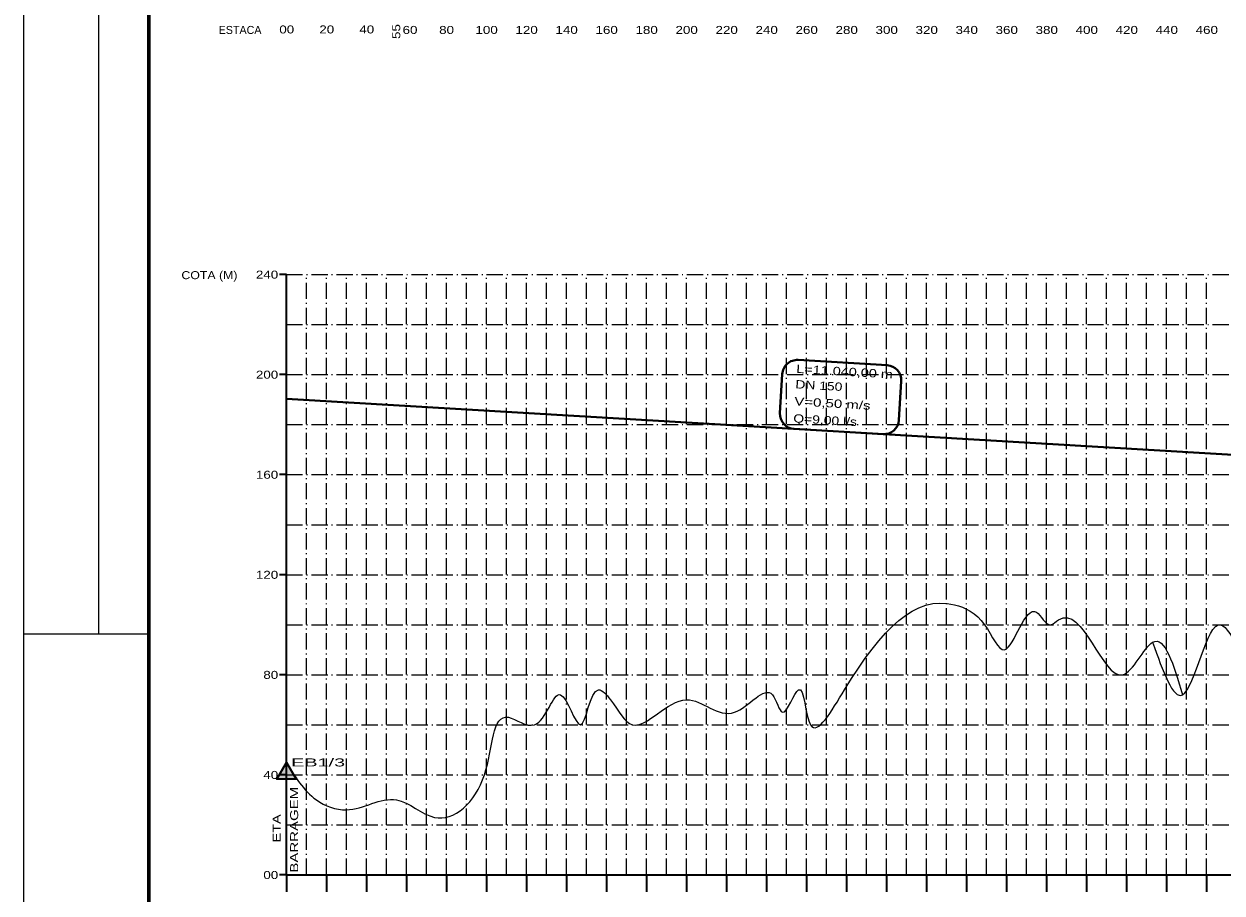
# Model space of a CAD drawing. Extents: x 0 to 1682, y 0 to 1188.
# Drawn here: x -0.2 to 478.9, y 490.3 to 837.7 of the extents above; entities that cross this region are included whole.
import ezdxf
from ezdxf.enums import TextEntityAlignment as Align

# ---------------------------------------------------------------- set-up
doc = ezdxf.new("R2010")
doc.units = 0
doc.header["$LTSCALE"] = 1.3
doc.linetypes.add('DOT_DASHED', pattern=[7.7, 5, -1.2, 0.3, -1.2])
for name, color, linetype, lineweight in [('1', 7, 'DOT_DASHED', 13), ('56', 7, 'Continuous', 13), ('62', 7, 'Continuous', 13), ('63', 7, 'Continuous', 25), ('9', 7, 'Continuous', 40)]:
    doc.layers.add(name, color=color, linetype=linetype, lineweight=lineweight)
doc.layers.add('24', color=7, linetype='Continuous')

msp = doc.modelspace()

# ---------------------------------------------------------------- hatches: boundary and pattern name
at = {"layer": '62'}
msp.add_hatch(color=256, dxfattribs=at).paths.add_polyline_path([(104.775, 542.538), (108.721, 535.8), (100.912, 535.751)])

# ---------------------------------------------------------------- linework, layer by layer
at = {"layer": '1'}
for p, q in [((104.775, 737.538), (914.356, 737.538)), ((112.775, 497.538), (112.775, 737.538)), ((120.775, 497.538), (120.775, 737.538)), ((128.775, 497.538), (128.775, 737.538)), ((136.775, 497.538), (136.775, 737.538)), ((144.775, 497.538), (144.775, 737.538)), ((152.775, 497.538), (152.775, 737.538)), ((160.775, 497.538), (160.775, 737.538)), ((168.775, 497.538), (168.775, 737.538)), ((176.775, 497.538), (176.775, 737.538)), ((184.775, 497.538), (184.775, 737.538)), ((192.775, 497.538), (192.775, 737.538)), ((200.775, 497.538), (200.775, 737.538)), ((208.775, 497.538), (208.775, 737.538)), ((216.775, 497.538), (216.775, 737.538)), ((224.775, 497.538), (224.775, 737.538)), ((232.775, 497.538), (232.775, 737.538)), ((240.775, 497.538), (240.775, 737.538)), ((248.775, 497.538), (248.775, 737.538)), ((256.775, 497.538), (256.775, 737.538)), ((264.775, 497.538), (264.775, 737.538)), ((272.775, 497.538), (272.775, 737.538)), ((280.775, 497.538), (280.775, 737.538)), ((288.775, 497.538), (288.775, 737.538)), ((296.775, 497.538), (296.775, 737.538)), ((304.775, 497.538), (304.775, 737.538)), ((312.775, 497.538), (312.775, 737.538)), ((320.775, 497.538), (320.775, 737.538)), ((328.775, 497.538), (328.775, 737.538)), ((336.775, 497.538), (336.775, 737.538)), ((344.775, 497.538), (344.775, 737.538)), ((352.775, 497.538), (352.775, 737.538)), ((360.775, 497.538), (360.775, 737.538)), ((368.775, 497.538), (368.775, 737.538)), ((376.775, 497.538), (376.775, 737.538)), ((384.775, 497.538), (384.775, 737.538)), ((392.775, 497.538), (392.775, 737.538)), ((400.775, 497.538), (400.775, 737.538)), ((408.775, 497.538), (408.775, 737.538)), ((416.775, 497.538), (416.775, 737.538)), ((424.775, 497.538), (424.775, 737.538)), ((432.775, 497.538), (432.775, 737.538)), ((440.775, 497.538), (440.775, 737.538)), ((448.775, 497.538), (448.775, 737.538)), ((456.775, 497.538), (456.775, 737.538)), ((464.775, 497.538), (464.775, 737.538)), ((472.775, 497.538), (472.775, 737.538)), ((104.775, 717.538), (914.356, 717.538)), ((104.775, 697.538), (914.356, 697.538)), ((104.775, 677.538), (914.356, 677.538)), ((104.775, 657.538), (914.356, 657.538)), ((104.775, 637.538), (914.356, 637.538)), ((104.775, 617.538), (914.356, 617.538)), ((104.775, 597.538), (914.356, 597.538)), ((104.775, 577.538), (914.356, 577.538)), ((104.775, 557.538), (914.356, 557.538)), ((104.775, 537.538), (914.356, 537.538)), ((104.775, 517.538), (914.356, 517.538))]:
    msp.add_line(p, q, dxfattribs=at)
at = {"layer": '56'}
for points in [[(104.775, 542.538), (116.775, 527.538), (128.775, 523.538), (148.775, 527.538), (163.975, 520.538), (183.975, 537.538), (193.575, 560.538), (203.975, 557.538), (214.375, 569.538), (222.375, 557.538), (229.575, 571.538), (234.375, 567.538), (243.175, 557.538), (264.775, 567.538), (283.975, 562.538), (299.175, 569.538), (303.175, 562.538), (309.575, 571.538), (314.375, 557.538), (327.975, 571.538), (371.975, 605.538), (383.975, 597.538), (391.975, 587.538), (404.775, 602.538), (410.375, 597.538), (413.575, 599.538), (439.175, 577.538), (451.175, 590.538), (463.175, 569.538)], [(451.175, 590.538), (463.175, 569.538), (478.375, 597.538), (486.375, 587.538), (511.175, 575.538), (515.175, 579.538), (526.375, 567.538), (546.375, 557.538)]]:
    msp.add_spline(points, degree=3, dxfattribs=at)
at = {"layer": '62', "lineweight": 35}
for p, q in [((104.775, 737.538), (102.044, 737.538)), ((104.607, 737.538), (104.775, 737.538)), ((104.775, 497.538), (104.775, 737.538)), ((104.607, 727.538), (104.775, 727.538)), ((104.607, 717.538), (104.775, 717.538)), ((104.607, 707.538), (104.775, 707.538)), ((104.775, 697.538), (102.044, 697.538)), ((104.607, 697.538), (104.775, 697.538)), ((104.607, 687.538), (104.775, 687.538)), ((104.607, 677.538), (104.775, 677.538)), ((104.607, 667.538), (104.775, 667.538)), ((104.775, 657.538), (102.044, 657.538)), ((104.607, 657.538), (104.775, 657.538)), ((104.607, 647.538), (104.775, 647.538)), ((104.607, 637.538), (104.775, 637.538)), ((104.607, 627.538), (104.775, 627.538)), ((104.775, 617.538), (102.044, 617.538)), ((104.607, 617.538), (104.775, 617.538)), ((104.607, 607.538), (104.775, 607.538)), ((104.607, 597.538), (104.775, 597.538)), ((104.607, 587.538), (104.775, 587.538)), ((104.775, 577.538), (102.044, 577.538)), ((104.607, 577.538), (104.775, 577.538)), ((104.607, 567.538), (104.775, 567.538)), ((104.607, 557.538), (104.775, 557.538)), ((104.607, 547.538), (104.775, 547.538)), ((104.775, 537.538), (102.044, 537.538)), ((104.607, 537.538), (104.775, 537.538)), ((104.607, 527.538), (104.775, 527.538)), ((104.607, 517.538), (104.775, 517.538)), ((104.607, 507.538), (104.775, 507.538)), ((104.775, 497.538), (102.044, 497.538)), ((104.775, 497.538), (104.775, 490.71)), ((104.775, 497.538), (914.356, 497.538)), ((120.775, 497.538), (120.775, 490.71)), ((136.775, 497.538), (136.775, 490.71)), ((152.775, 497.538), (152.775, 490.71)), ((168.775, 497.538), (168.775, 490.71)), ((184.775, 497.538), (184.775, 490.71)), ((200.775, 497.538), (200.775, 490.71)), ((216.775, 497.538), (216.775, 490.71)), ((232.775, 497.538), (232.775, 490.71)), ((248.775, 497.538), (248.775, 490.71)), ((264.775, 497.538), (264.775, 490.71)), ((280.775, 497.538), (280.775, 490.71)), ((296.775, 497.538), (296.775, 490.71)), ((312.775, 497.538), (312.775, 490.71)), ((328.775, 497.538), (328.775, 490.71)), ((344.775, 497.538), (344.775, 490.71)), ((360.775, 497.538), (360.775, 490.71)), ((376.775, 497.538), (376.775, 490.71)), ((392.775, 497.538), (392.775, 490.71)), ((408.775, 497.538), (408.775, 490.71)), ((424.775, 497.538), (424.775, 490.71)), ((440.775, 497.538), (440.775, 490.71)), ((456.775, 497.538), (456.775, 490.71)), ((472.775, 497.538), (472.775, 490.71))]:
    msp.add_line(p, q, dxfattribs=at)
at = {"layer": '62'}
for p, q in [((104.607, 735.538), (104.775, 735.538)), ((104.607, 733.538), (104.775, 733.538)), ((104.607, 731.538), (104.775, 731.538)), ((104.607, 729.538), (104.775, 729.538)), ((104.607, 725.538), (104.775, 725.538)), ((104.607, 723.538), (104.775, 723.538)), ((104.607, 721.538), (104.775, 721.538)), ((104.607, 719.538), (104.775, 719.538)), ((104.607, 715.538), (104.775, 715.538)), ((104.607, 713.538), (104.775, 713.538)), ((104.607, 711.538), (104.775, 711.538)), ((104.607, 709.538), (104.775, 709.538)), ((104.607, 705.538), (104.775, 705.538)), ((104.607, 703.538), (104.775, 703.538)), ((104.607, 701.538), (104.775, 701.538)), ((104.607, 699.538), (104.775, 699.538)), ((104.607, 695.538), (104.775, 695.538)), ((104.607, 693.538), (104.775, 693.538)), ((104.607, 691.538), (104.775, 691.538)), ((104.607, 689.538), (104.775, 689.538)), ((104.607, 685.538), (104.775, 685.538)), ((104.607, 683.538), (104.775, 683.538)), ((104.607, 681.538), (104.775, 681.538)), ((104.607, 679.538), (104.775, 679.538)), ((104.607, 675.538), (104.775, 675.538)), ((104.607, 673.538), (104.775, 673.538)), ((104.607, 671.538), (104.775, 671.538)), ((104.607, 669.538), (104.775, 669.538)), ((104.607, 665.538), (104.775, 665.538)), ((104.607, 663.538), (104.775, 663.538)), ((104.607, 661.538), (104.775, 661.538)), ((104.607, 659.538), (104.775, 659.538)), ((104.607, 655.538), (104.775, 655.538)), ((104.607, 653.538), (104.775, 653.538)), ((104.607, 651.538), (104.775, 651.538)), ((104.607, 649.538), (104.775, 649.538)), ((104.607, 645.538), (104.775, 645.538)), ((104.607, 643.538), (104.775, 643.538)), ((104.607, 641.538), (104.775, 641.538)), ((104.607, 639.538), (104.775, 639.538)), ((104.607, 635.538), (104.775, 635.538)), ((104.607, 633.538), (104.775, 633.538)), ((104.607, 631.538), (104.775, 631.538)), ((104.607, 629.538), (104.775, 629.538)), ((104.607, 625.538), (104.775, 625.538)), ((104.607, 623.538), (104.775, 623.538)), ((104.607, 621.538), (104.775, 621.538)), ((104.607, 619.538), (104.775, 619.538)), ((104.607, 615.538), (104.775, 615.538)), ((104.607, 613.538), (104.775, 613.538)), ((104.607, 611.538), (104.775, 611.538)), ((104.607, 609.538), (104.775, 609.538)), ((104.607, 605.538), (104.775, 605.538)), ((104.607, 603.538), (104.775, 603.538)), ((104.607, 601.538), (104.775, 601.538)), ((104.607, 599.538), (104.775, 599.538)), ((104.607, 595.538), (104.775, 595.538)), ((104.607, 593.538), (104.775, 593.538)), ((104.607, 591.538), (104.775, 591.538)), ((104.607, 589.538), (104.775, 589.538)), ((104.607, 585.538), (104.775, 585.538)), ((104.607, 583.538), (104.775, 583.538)), ((104.607, 581.538), (104.775, 581.538)), ((104.607, 579.538), (104.775, 579.538)), ((104.607, 575.538), (104.775, 575.538)), ((104.607, 573.538), (104.775, 573.538)), ((104.607, 571.538), (104.775, 571.538)), ((104.607, 569.538), (104.775, 569.538)), ((104.607, 565.538), (104.775, 565.538)), ((104.607, 563.538), (104.775, 563.538)), ((104.607, 561.538), (104.775, 561.538)), ((104.607, 559.538), (104.775, 559.538)), ((104.607, 555.538), (104.775, 555.538)), ((104.607, 553.538), (104.775, 553.538)), ((104.607, 551.538), (104.775, 551.538)), ((104.607, 549.538), (104.775, 549.538)), ((104.607, 545.538), (104.775, 545.538)), ((104.607, 543.538), (104.775, 543.538)), ((104.607, 541.538), (104.775, 541.538)), ((104.607, 539.538), (104.775, 539.538)), ((104.607, 535.538), (104.775, 535.538)), ((104.607, 533.538), (104.775, 533.538)), ((104.607, 531.538), (104.775, 531.538)), ((104.607, 529.538), (104.775, 529.538)), ((104.607, 525.538), (104.775, 525.538)), ((104.607, 523.538), (104.775, 523.538)), ((104.607, 521.538), (104.775, 521.538)), ((104.607, 519.538), (104.775, 519.538)), ((104.607, 515.538), (104.775, 515.538)), ((104.607, 513.538), (104.775, 513.538)), ((104.607, 511.538), (104.775, 511.538)), ((104.607, 509.538), (104.775, 509.538)), ((104.607, 505.538), (104.775, 505.538)), ((104.607, 503.538), (104.775, 503.538)), ((104.607, 501.538), (104.775, 501.538)), ((104.607, 499.538), (104.775, 499.538))]:
    msp.add_line(p, q, dxfattribs=at)
at = {"layer": '62', "lineweight": 35}
msp.add_lwpolyline([(104.775, 542.538), (108.721, 535.8), (100.912, 535.751)], close=True, dxfattribs=at)
at = {"layer": '63'}
for p, q in [((-0.168, -0.119), (-0.168, 1187.881)), ((29.832, 593.881), (29.832, 1187.881)), ((-0.168, 593.881), (49.832, 593.881))]:
    msp.add_line(p, q, dxfattribs=at)
at = {"layer": '63', "lineweight": 60}
msp.add_lwpolyline([(951.544, 19.881), (49.832, 19.881), (49.832, 1167.881)], dxfattribs=at)
at = {"layer": '9'}
for p, q in [((309.42, 703.383), (344.992, 701.277)), ((303.076, 697.748), (302.154, 682.165)), ((350.627, 694.933), (349.705, 679.35)), ((307.789, 675.82), (343.361, 673.715))]:
    msp.add_line(p, q, dxfattribs=at)
msp.add_lwpolyline([(104.775, 687.838), (546.375, 661.698), (914.356, 602.538)], dxfattribs=at)
for centre, start, end in [((309.066, 697.393), 86.61239, 176.61239), ((344.638, 695.288), 356.61239, 86.61239), ((308.143, 681.81), 176.61239, 266.61239), ((343.715, 679.704), 266.61239, 356.61239)]:
    msp.add_arc(centre, 6, start, end, dxfattribs=at)

# ---------------------------------------------------------------- texts
at = {"layer": '24'}
msp.add_text('ESTACA', height=3.2, dxfattribs=at).set_placement((86.25, 833.708), align=Align.CENTER)
at = {"layer": '24', "width": 1.25}
for s, p in [('00', (104.915, 833.905)), ('20', (120.915, 833.905)), ('40', (136.915, 833.905)), ('60', (154.212, 833.708)), ('80', (168.84, 833.708)), ('100', (184.84, 833.708)), ('120', (200.84, 833.708)), ('140', (216.84, 833.708)), ('160', (232.84, 833.708)), ('180', (248.84, 833.708)), ('200', (264.84, 833.708)), ('220', (280.84, 833.708)), ('240', (296.84, 833.708)), ('260', (312.84, 833.708)), ('280', (328.84, 833.708)), ('300', (344.84, 833.708)), ('320', (360.84, 833.708)), ('340', (376.84, 833.708)), ('360', (392.84, 833.708)), ('380', (408.84, 833.708)), ('400', (424.84, 833.708)), ('420', (440.84, 833.708)), ('440', (456.84, 833.708)), ('460', (472.84, 833.708))]:
    msp.add_text(s, height=3.2, dxfattribs=at).set_placement(p, align=Align.CENTER)
msp.add_text('55', height=3.2, rotation=90, dxfattribs=at).set_placement((150.311, 834.668), align=Align.CENTER)
at = {"layer": '24'}
for s, width, p in [('COTA (M)', 1.15, (85.214, 735.682)), ('240', 1.25, (101.506, 735.898)), ('200', 1.25, (101.506, 695.898)), ('160', 1.25, (101.506, 655.898)), ('120', 1.25, (101.506, 615.898)), ('80', 1.25, (101.506, 575.898)), ('40', 1.25, (101.506, 535.898)), ('00', 1.25, (101.506, 495.898))]:
    msp.add_text(s, height=3.2, dxfattribs=dict(at, width=width)).set_placement(p, align=Align.RIGHT)
at = {"layer": '24', "width": 1.85}
msp.add_text('EB1/3', height=3.2, dxfattribs=at).set_placement((106.682, 540.901))
at = {"layer": '24'}
for s, width, p in [('BARRAGEM', 1.4, (109.479, 498.451)), ('ETA', 1.35, (102.482, 510.508))]:
    msp.add_text(s, height=3.2, rotation=90, dxfattribs=dict(at, width=width)).set_placement(p)
at = {"layer": '9'}
for s, width, p in [('L=11.040,00 m', 1.3, (308.6, 698.244)), ('DN 150', 1.25, (308.235, 692.075)), ('V=0,50 m/s', 1.35, (307.832, 685.263)), ('Q=9,00 l/s', 1.25, (307.428, 678.451))]:
    msp.add_text(s, height=3.319, rotation=356.612, dxfattribs=dict(at, width=width)).set_placement(p)

doc.saveas('drawing.dxf')
